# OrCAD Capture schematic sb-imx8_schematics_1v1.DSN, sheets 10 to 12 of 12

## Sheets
10 07. CSI, USB OTG, PCIe: size C; title: 07. CSI, USB OTG, PCIe
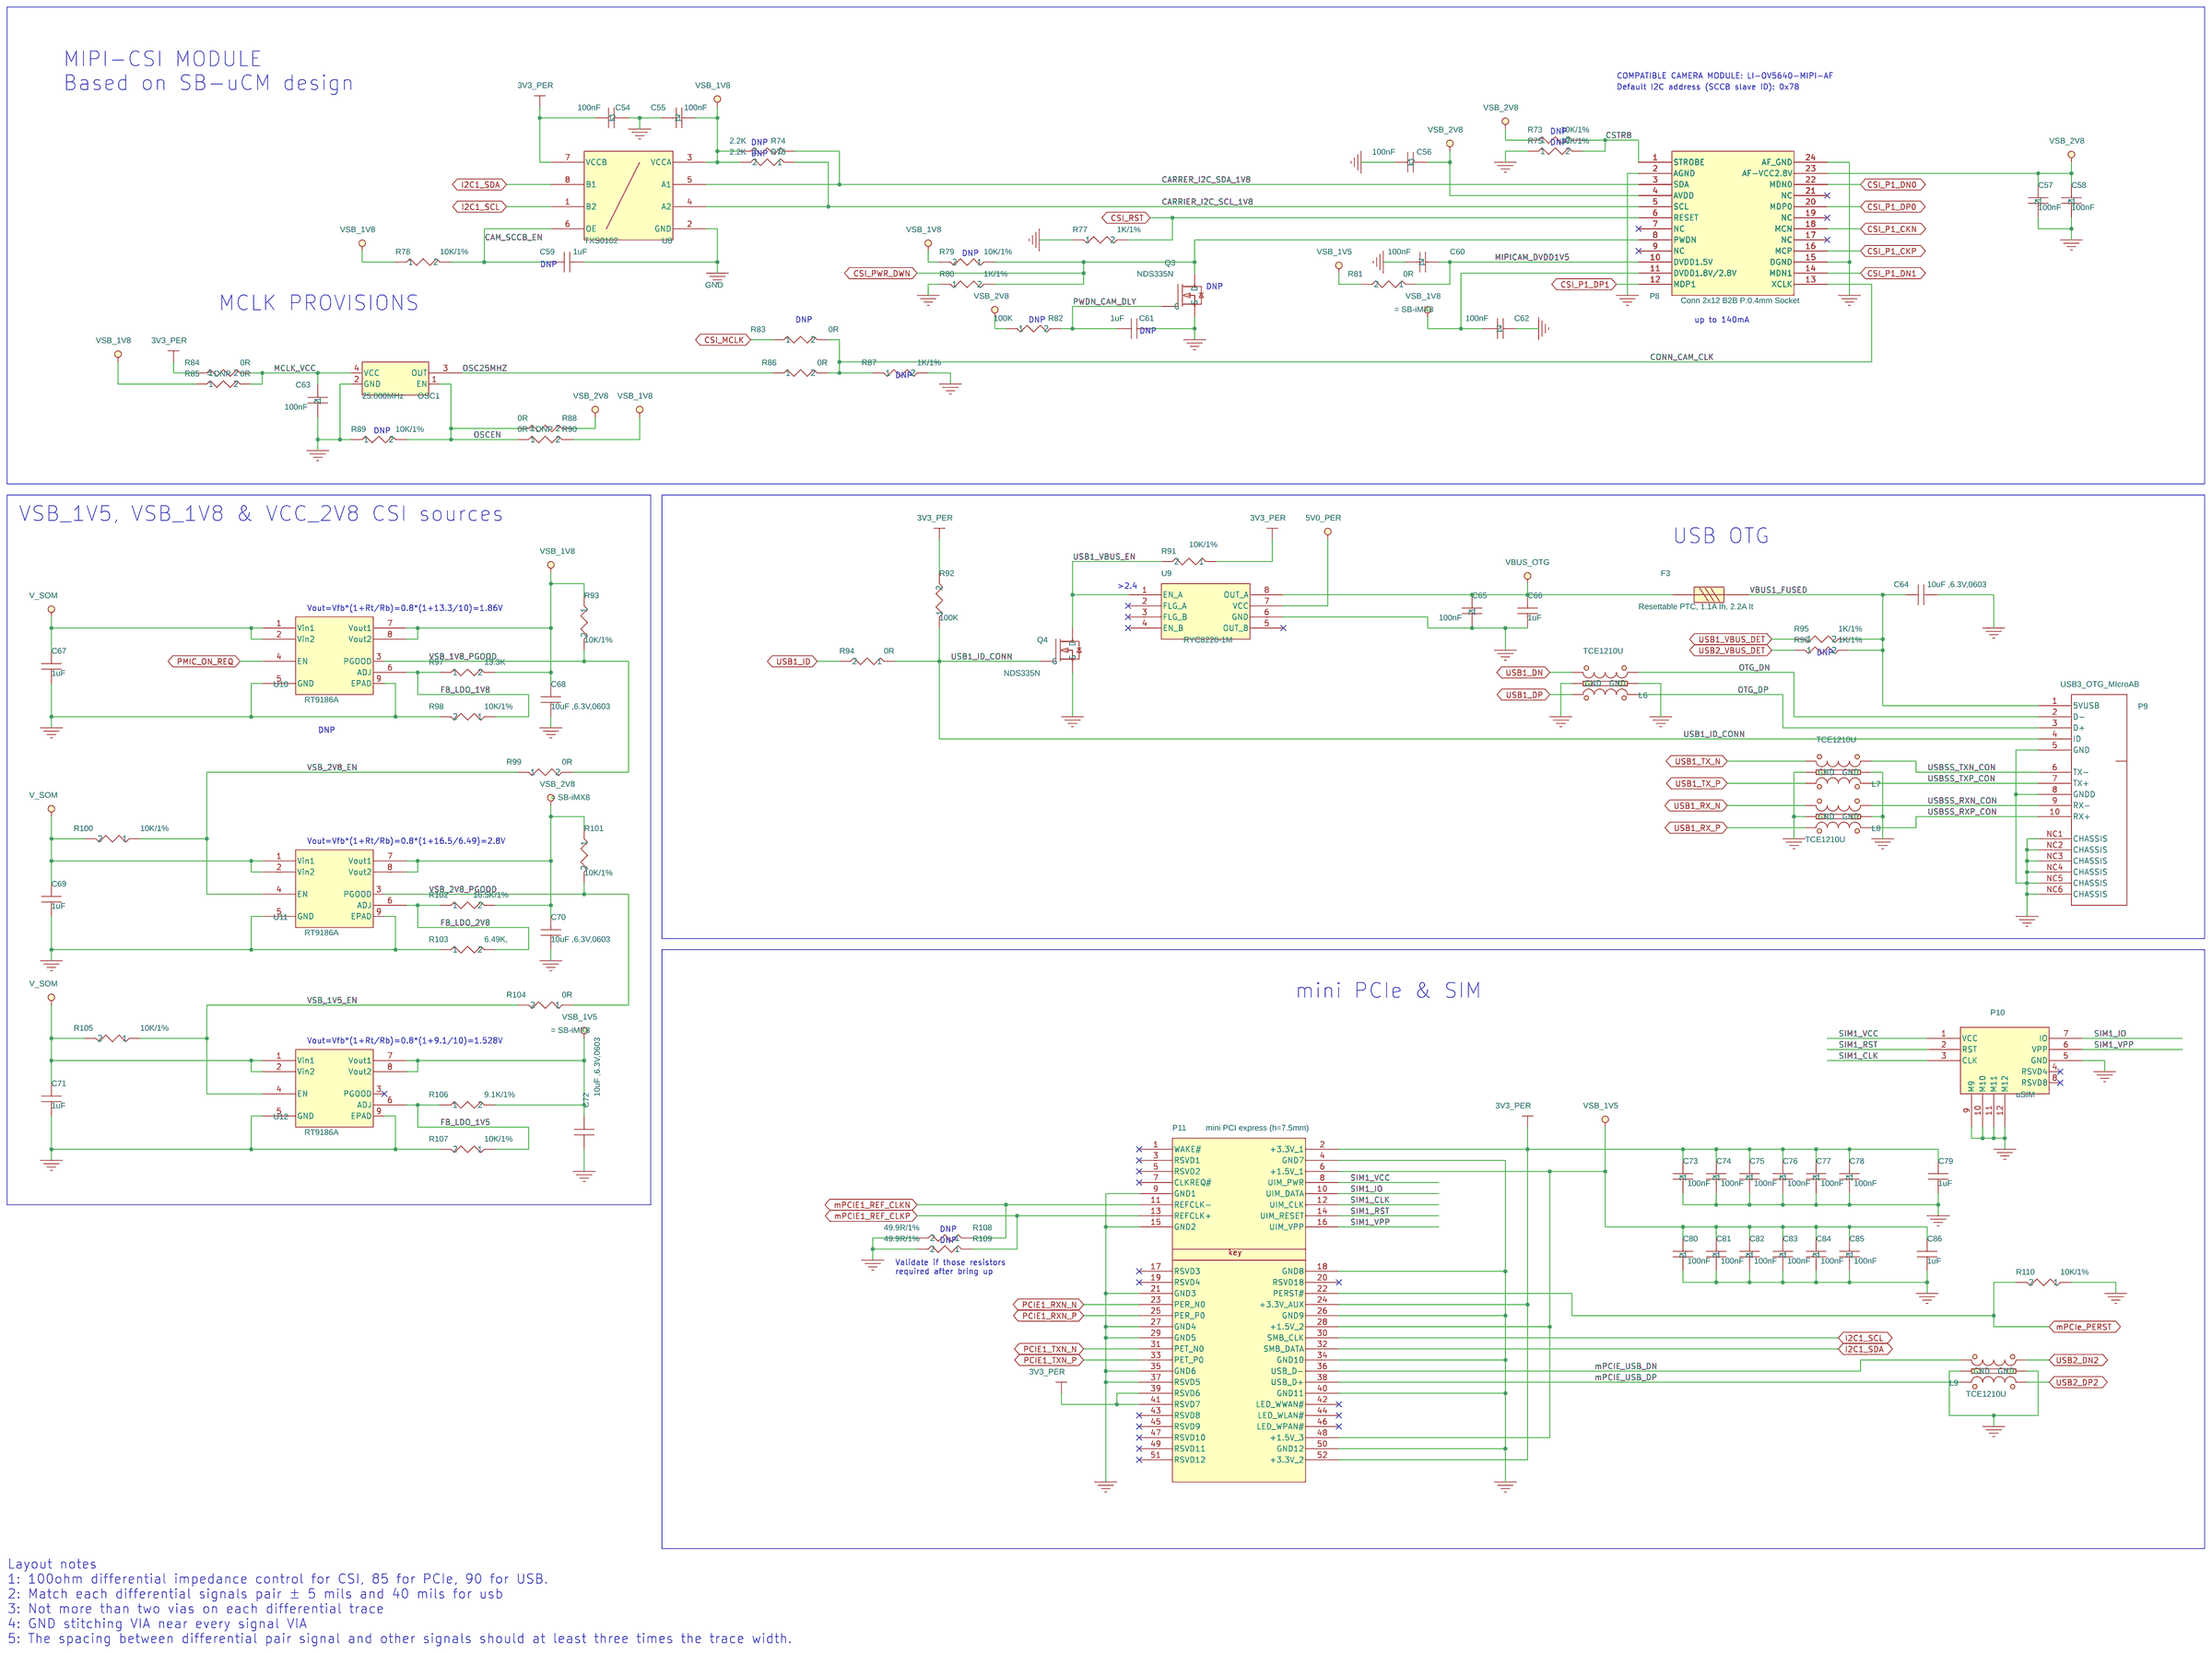
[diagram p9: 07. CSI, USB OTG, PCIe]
11 08. UART, RS232, RS485, EEPROM: size C; title: 08. UART, RS232, RS485, EEPROM
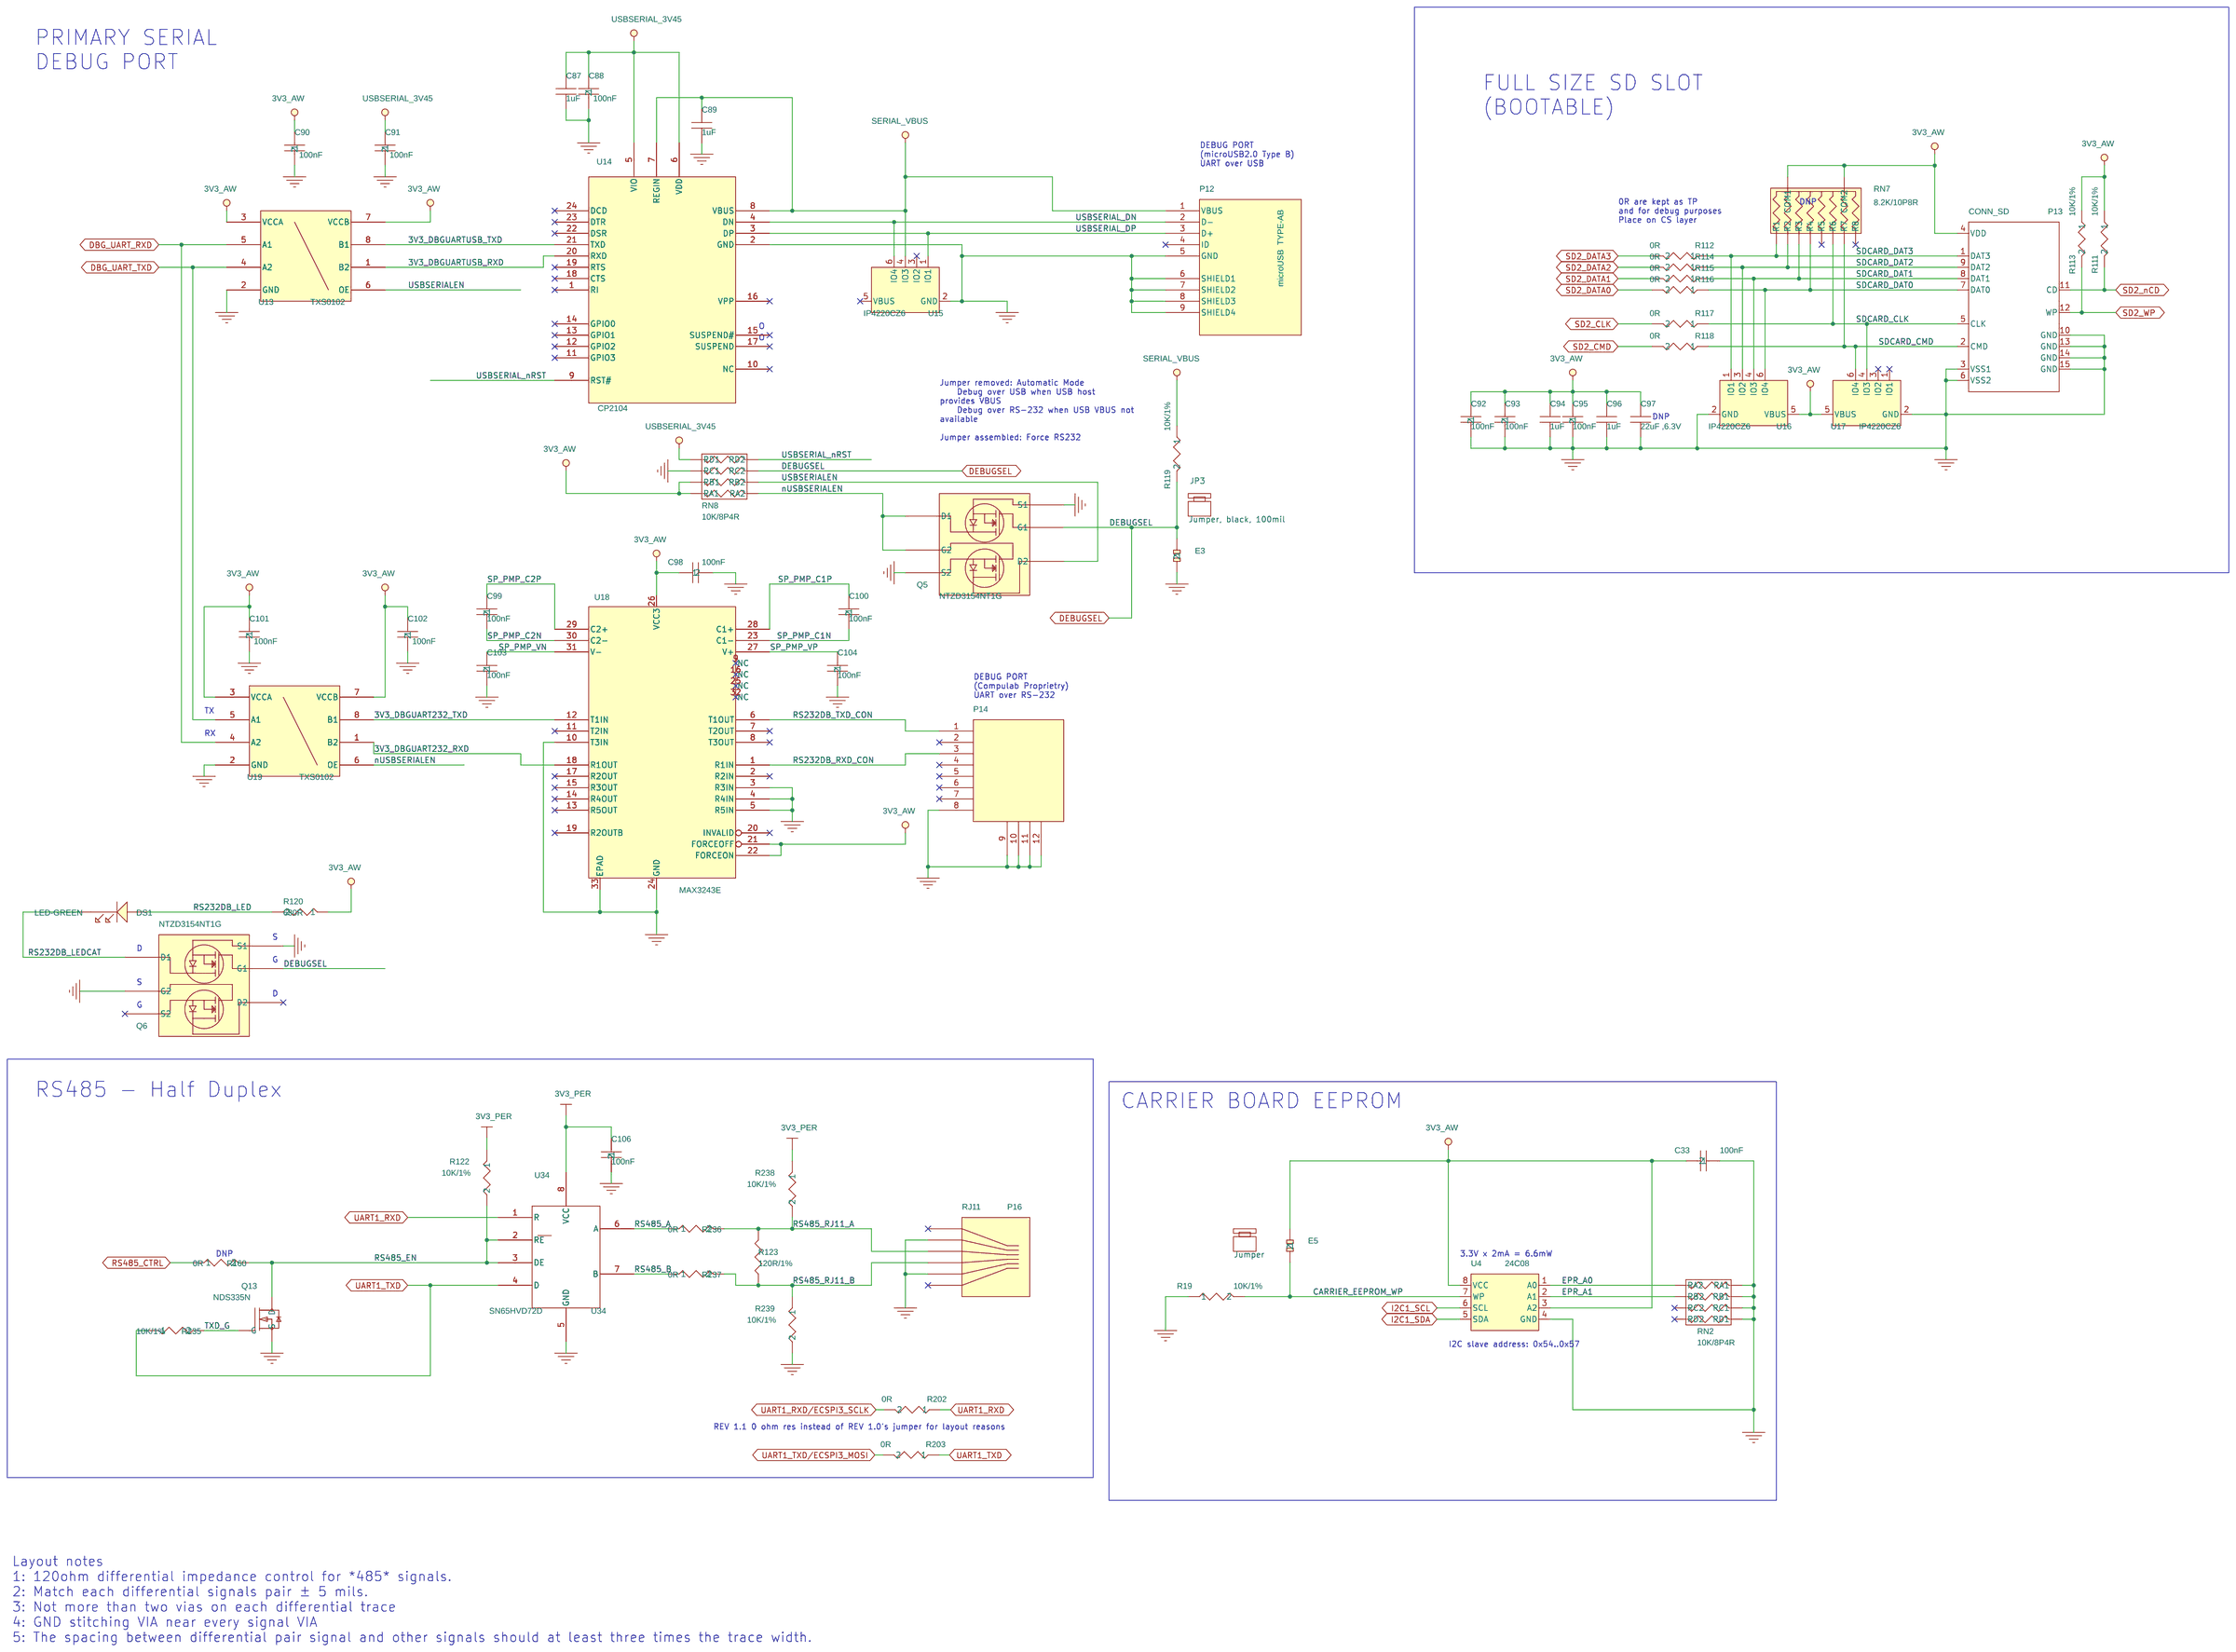
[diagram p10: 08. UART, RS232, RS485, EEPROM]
12 09. Power: size B; title: 09. Power
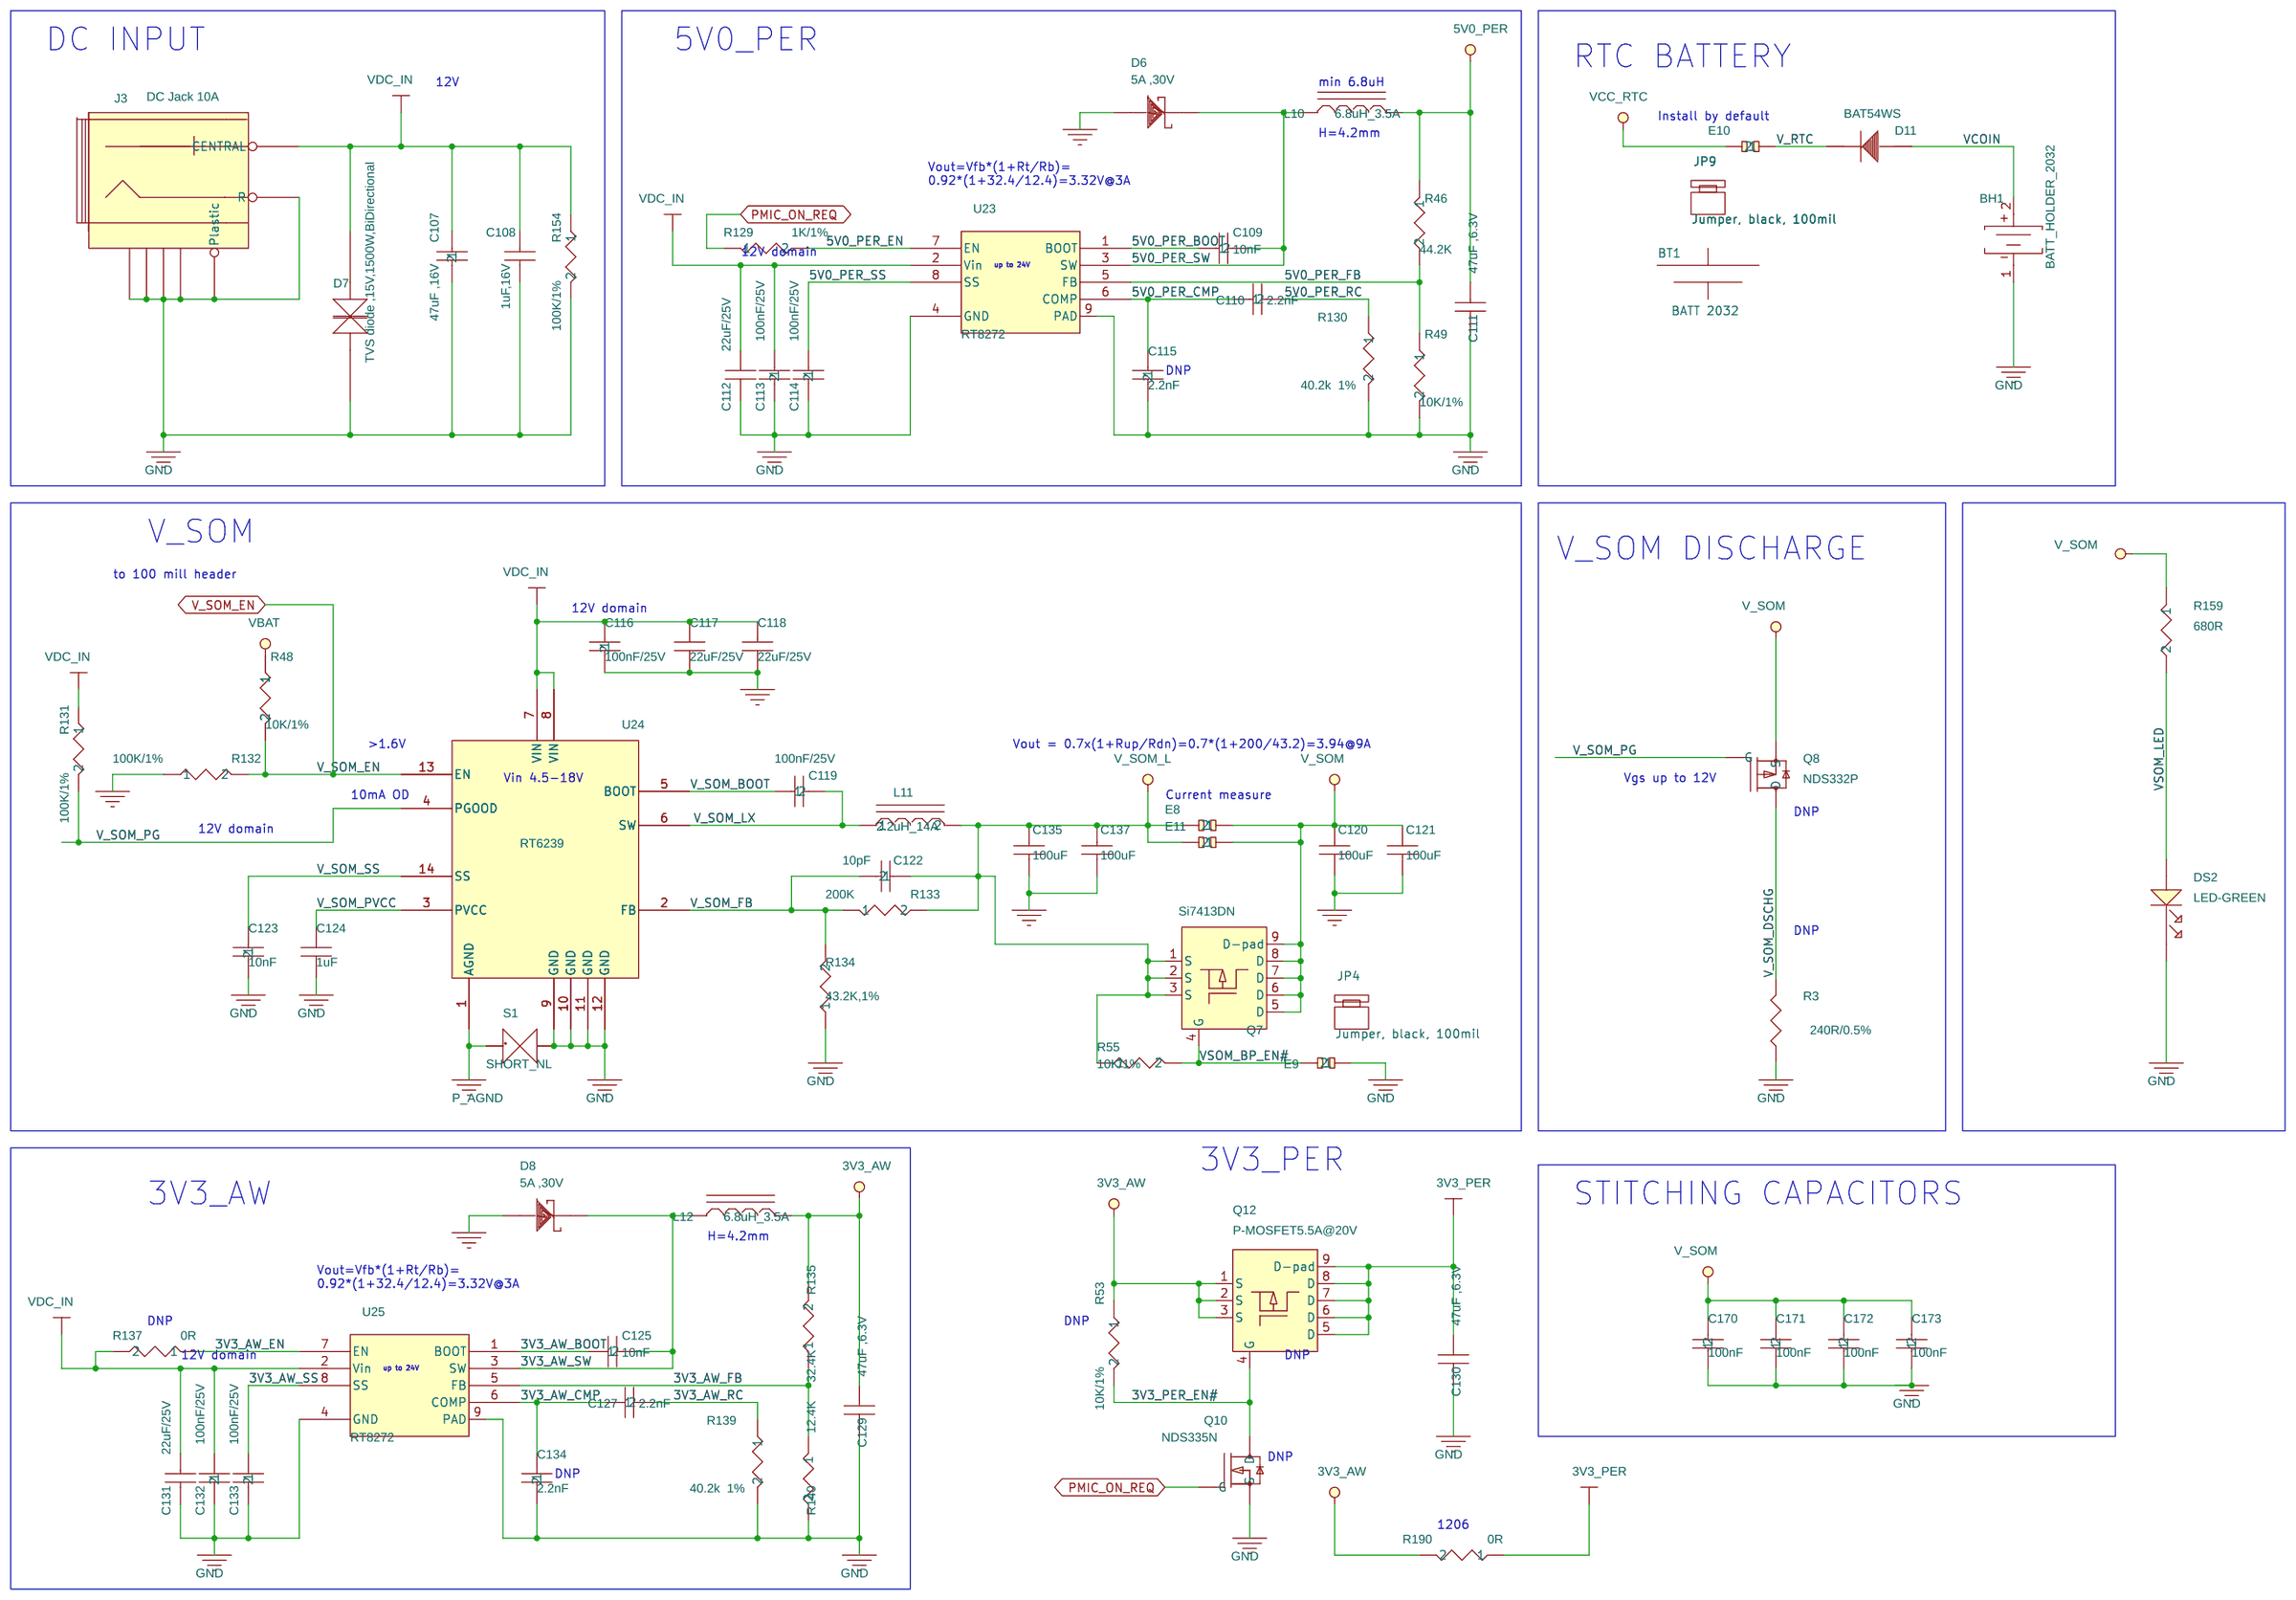
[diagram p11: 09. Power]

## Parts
sheet 07. CSI, USB OTG, PCIe
C54  100nF  [RC0402]
C55  100nF  [RC0402]
C56  100nF  [RC0402]
C57  100nF  [RC0402]
C58  100nF  [RC0402]
C59  1uF  [RC0402]
C60  100nF  [RC0402]
C61  1uF  [RC0402]
C62  100nF  [RC0402]
C63  100nF  [RC0402]
C64  10uF ,6.3V,0603  [C0603-08]
C65  100nF  [RC0402]
C66  1uF  [RC0402]
C67  1uF  [RC0402]
C68  10uF ,6.3V,0603  [C0603-08]
C69  1uF  [RC0402]
C70  10uF ,6.3V,0603  [C0603-08]
C71  1uF  [RC0402]
C72  10uF ,6.3V,0603  [C0603-08]
C73  100nF  [RC0402]
C74  100nF  [RC0402]
C75  100nF  [RC0402]
C76  100nF  [RC0402]
C77  100nF  [RC0402]
C78  100nF  [RC0402]
C79  1uF  [RC0402]
C80  100nF  [RC0402]
C81  100nF  [RC0402]
C82  100nF  [RC0402]
C83  100nF  [RC0402]
C84  100nF  [RC0402]
C85  100nF  [RC0402]
C86  1uF  [RC0402]
F3  Resettable PTC, 1.1A Ih, 2.2A It  [FUSE-1206]
L6  TCE1210U  [EMI1012-ESD]
L7  TCE1210U  [EMI1012-ESD]
L8  TCE1210U  [EMI1012-ESD]
L9  TCE1210U  [EMI1012-ESD]
OSC1  25.000MHz  [OSC3225]
P8  Conn 2x12 B2B P:0.4mm Socket  [B2B04M2X12R]
P9  USB3_OTG_MIcroAB  [MICRO-USB3-AB-RA-SM]
P10  uSIM  [SKT-MicroSIM6-SM]
P11  mini PCI express (h=7.5mm)  [MINIPCIE-4]
Q3  NDS335N  [SOT23]
Q4  NDS335N  [SOT23]
R73  10K/1%  [RC0402]
R74  2.2K  [RC0402]
R75  10K/1%  [RC0402]
R76  2.2K  [RC0402]
R77  1K/1%  [RC0402]
R78  10K/1%  [RC0402]
R79  10K/1%  [RC0402]
R80  1K/1%  [RC0402]
R81  0R  [RC0402]
R82  100K  [RC0402]
R83  0R  [RC0402]
R84  0R  [RC0402]
R85  0R  [RC0402]
R86  0R  [RC0402]
R87  1K/1%  [RC0402]
R88  0R  [RC0402]
R89  10K/1%  [RC0402]
R90  0R  [RC0402]
R91  10K/1%  [RC0402]
R92  100K  [RC0402]
R93  10K/1%  [RC0402]
R94  0R  [RC0402]
R95  1K/1%  [RC0402]
R96  1K/1%  [RC0402]
R97  13.3K  [RC0402]
R98  10K/1%  [RC0402]
R99  0R  [RC0402]
R100  10K/1%  [RC0402]
R101  10K/1%  [RC0402]
R102  16.5K/1%  [RC0402]
R103  6.49K,  [RC0402]
R104  0R  [RC0402]
R105  10K/1%  [RC0402]
R106  9.1K/1%  [RC0402]
R107  10K/1%  [RC0402]
R108  49.9R/1%  [RC0402]
R109  49.9R/1%  [RC0402]
R110  10K/1%  [RC0402]
U8  TXS0102  [MO-187DA-8]
U9  RYC8220-1M  [SO-8-150]
U10  RT9186A  [DFN3x3-8]
U11  RT9186A  [DFN3x3-8]
U12  RT9186A  [DFN3x3-8]
sheet 08. UART, RS232, RS485, EEPROM
C33  100nF  [RC0402]
C87  1uF  [RC0402]
C88  100nF  [RC0402]
C89  1uF  [RC0402]
C90  100nF  [RC0402]
C91  100nF  [RC0402]
C92  100nF  [RC0402]
C93  100nF  [RC0402]
C94  1uF  [RC0402]
C95  100nF  [RC0402]
C96  1uF  [RC0402]
C97  22uF ,6.3V  [RC0603]
C98  100nF  [RC0402]
C99  100nF  [RC0402]
C100  100nF  [RC0402]
C101  100nF  [RC0402]
C102  100nF  [RC0402]
C103  100nF  [RC0402]
C104  100nF  [RC0402]
C106  100nF  [RC0402]
DS1  LED-GREEN  [LED-1206]
E3  HDR1X2  [1X2THHDR]
E5  HDR1X2  [1X2THHDR]
JP3  Jumper, black, 100mil
JP10  Jumper
P12  microUSB  TYPE-AB  [MICRO-USB-AB-RA-SM]
P13  CONN_SD  [SD-RA-SM]
P14  Ultra Mini Serial Connector  [UMS-8]
P16  RJ11  [RJ11TH6-6]
Q5  NTZD3154NT1G  [SOT-563]
Q6  NTZD3154NT1G  [SOT-563]
Q13  NDS335N  [SOT23]
R19  10K/1%  [RC0402]
R111  10K/1%  [RC0402]
R112  0R  [RC0402]
R113  10K/1%  [RC0402]
R114  0R  [RC0402]
R115  0R  [RC0402]
R116  0R  [RC0402]
R117  0R  [RC0402]
R118  0R  [RC0402]
R119  10K/1%  [RC0402]
R120  680R  [RC0402]
R122  10K/1%  [RC0402]
R123  120R/1%  [RC0603]
R160  0R  [RC0402]
R202  0R  [RC0402]
R203  0R  [RC0402]
R235  10K/1%  [RC0402]
R236  0R  [RC0402]
R237  0R  [RC0402]
R238  10K/1%  [RC0402]
R239  10K/1%  [RC0402]
RN2  10K/8P4R  [RESNET8P0805]
RN7  8.2K/10P8R  [RESNET10P1206]
RN8  10K/8P4R  [RESNET8P0805]
U4  24C08  [MO-229VCED-2]
U13  TXS0102  [MO-187DA-8]
U14  CP2104  [MO-220VGGD-8]
U15  IP4220CZ6  [SOT23-6L]
U16  IP4220CZ6  [SOT23-6L]
U17  IP4220CZ6  [SOT23-6L]
U18  MAX3243E  [QFN5x5-32]
U19  TXS0102  [MO-187DA-8]
U34  SN65HVD72D  [MSOP-8]
sheet 09. Power
BH1  BATT_HOLDER_2032  [BATTH20MM]
BT1  BATT 2032
C107  47uF ,16V  [C1210H2_5]
C108  1uF,16V  [RC0402]
C109  10nF  [RC0402]
C110  2.2nF  [RC0402]
C111  47uF ,6.3V  [C0805]
C112  22uF/25V  [C0805]
C113  100nF/25V  [RC0402]
C114  100nF/25V  [RC0402]
C115  2.2nF  [RC0402]
C116  100nF/25V  [RC0402]
C117  22uF/25V  [C0805]
C118  22uF/25V  [C0805]
C119  100nF/25V  [RC0402]
C120  100uF  [C1210H2_5]
C121  100uF  [C1210H2_5]
C122  10pF  [RC0402]
C123  10nF  [RC0402]
C124  1uF  [RC0402]
C125  10nF  [RC0402]
C127  2.2nF  [RC0402]
C129  47uF ,6.3V  [C0805]
C130  47uF ,6.3V  [C0805]
C131  22uF/25V  [C0805]
C132  100nF/25V  [RC0402]
C133  100nF/25V  [RC0402]
C134  2.2nF  [RC0402]
C135  100uF  [C1210H2_5]
C137  100uF  [C1210H2_5]
C170  100nF  [RC0402]
C171  100nF  [RC0402]
C172  100nF  [RC0402]
C173  100nF  [RC0402]
D6  5A ,30V  [SOD-128]
D7  TVS diode ,15V,1500W,BiDirectional  [DO-214AB]
D8  5A ,30V  [SOD-128]
D11  BAT54WS  [SOD-323]
DS2  LED-GREEN  [LED-1206]
E8  HDR1X2  [1X2THHDR]
E9  HDR1X2  [1X2THHDR]
E10  HDR1X2  [1X2THHDR]
E11  HDR1X2  [1X2THHDR]
J3  DC Jack 10A  [PJ-0810-TH]
JP4  Jumper, black, 100mil
JP9  Jumper, black, 100mil
L10  6.8uH_3.5A  [IND8_2x8_2]
L11  2.2uH_14A  [IND7x7_2SM]
L12  6.8uH_3.5A  [IND8_2x8_2]
Q7  Si7413DN  [Powerpak1212-8]
Q8  NDS332P  [SOT23]
Q10  NDS335N  [SOT23]
Q12  P-MOSFET5.5A@20V  [Powerpak1212-8]
R3  240R/0.5%  [RC0402]
R46  44.2K  [RC0402]
R48  10K/1%  [RC0402]
R49  10K/1%  [RC0402]
R53  10K/1%  [RC0402]
R55  10K/1%  [RC0402]
R129  1K/1%  [RC0402]
R130  40.2k  1%  [RC0402]
R131  100K/1%  [RC0402]
R132  100K/1%  [RC0402]
R133  200K  [RC0402]
R134  43.2K,1%  [RC0402]
R135  32.4K  [RC0402]
R137  0R  [RC0402]
R139  40.2k  1%  [RC0402]
R140  12.4K  [RC0402]
R154  100K/1%  [RC0402]
R159  680R  [RC0402]
R190  0R  [RC1206]
S1  SHORT_NL  [SHORT_NL]
U23  RT8272  [PSOP-8-2X2]
U24  RT6239  [uQFN2x3-14]
U25  RT8272  [PSOP-8-2X2]

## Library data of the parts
C54 C95 C173 = 100nF,_10V,_X7R,_10%,_0402_1: CLABCONF0: = SB-iMX8
C55 = 100nF,_10V,_X7R,_10%,_0402_15: CLABCONF0: = SB-iMX8
C56 C100 = 100nF,_10V,_X7R,_10%,_0402_8: CLABCONF0: = SB-iMX8
C57 C102 = 100nF,_10V,_X7R,_10%,_0402_6: CLABCONF0: = SB-iMX8
C58 C99 = 100nF,_10V,_X7R,_10%,_0402_9: CLABCONF0: = SB-iMX8
C59 C61 = 1uF,X5R,6.3V,0402: CLABCONF0: = DNP
C60 = 100nF,_10V,_X7R,_10%,_0402_20: CLABCONF0: = SB-iMX8
C62 C88 = 100nF,_10V,_X7R,_10%,_0402_14: CLABCONF0: = SB-iMX8
C63 C92 = 100nF,_10V,_X7R,_10%,_0402_13: CLABCONF0: = SB-iMX8
C64 C68 C70 C72 = 10uF,6_0.3V,0603,20%X5R: CLABCONF0: = SB-iMX8
C65 = 100nF,_10V,_X7R,_10%,_0402_19: CLABCONF0: = SB-iMX8
C66 C67 C69 C71 C79 C86 C87 C89 C94 C96 = 1uF,X5R,6.3V,0402: CLABCONF0: = SB-iMX8
C73 C103 = 100nF,_10V,_X7R,_10%,_0402_5: CLABCONF0: = SB-iMX8
C74 = 100nF,_10V,_X7R,_10%,_0402_18: CLABCONF0: = SB-iMX8
C75 = 100nF,_10V,_X7R,_10%,_0402_17: CLABCONF0: = SB-iMX8
C33 C76 = 100nF,_10V,_X7R,_10%,_0402_4: CLABCONF0: = SB-iMX8
C77 C98 C171 = 100nF,_10V,_X7R,_10%,_0402_3: CLABCONF0: = SB-iMX8
C78 C104 = 100nF,_10V,_X7R,_10%,_0402_7: CLABCONF0: = SB-iMX8
C80 C93 = 100nF,_10V,_X7R,_10%,_0402_11: CLABCONF0: = SB-iMX8
C81 C106 = 100nF,_10V,_X7R,_10%,_0402_10: CLABCONF0: = SB-iMX8
C82 C91 = 100nF,_10V,_X7R,_10%,_0402_12: CLABCONF0: = SB-iMX8
C83 C90 C172 = 100nF,_10V,_X7R,_10%,_0402: CLABCONF0: = SB-iMX8
C84 C101 C170 = 100nF,_10V,_X7R,_10%,_0402_2: CLABCONF0: = SB-iMX8
C85 = 100nF,_10V,_X7R,_10%,_0402_16: CLABCONF0: = SB-iMX8
F3 = Fuse,_0.75A_Ih,_1.5A_It: CLABCONF0: = SB-iMX8; P/N: 175P22200S
L6-L9 = ESD_CHOKE_DIFFx2_10: CLABCONF0: = SB-iMX8; P/N: 142D11801S
OSC1 = Osc.,_50Mhz,50PPM,_3.3V: CLABCONF0: = SB-iMX8; P/N: 141C25601S
P8 = Conn_2x12_B2B_P_0.4mm_Socket: CLABCONF0: = SB-iMX8; P/N: 182K02401S
P9 = USB3_OTGMINIB_5: CLABCONF0: = SB-iMX8; P/N: 180K01000S
P10 = uSIM_SOCKET_0: CLABCONF0: = SB-iMX8
P11 = mini_PCIe_0: CLABCONF0: = SB-iMX8; P/N: 182K05201S
Q3 Q10 Q13 = N-MOSFET,NDS335N,100mOhm@2.5V: CLABCONF0: DNP
Q4 = N-MOSFET,NDS335N,100mOhm@2.5V: CLABCONF0: = SB-iMX8
R73 = 10K,1%,0402,1_16W: CLABCONF0: = DNP
R74 = 2.2K,5%,0402.1_16W: CLABCONF0: DNP
R75 = 10K,1%,0402,1_16W_11: CLABCONF0: = DNP
R76 = 2.2K,5%,0402.1_16W_1: CLABCONF0: DNP
R77 = 1K,1%,0402,1_16W_1: CLABCONF0: = SB-iMX8; Group: CAN
R78 R122 = 10K,1%,0402,1_16W_5: CLABCONF0: = SB-iMX8
R79 = 10K,1%,0402,1_16W_2: CLABCONF0: = DNP
R80 R129 = 1K,1%,0402,1_16W: CLABCONF0: = SB-iMX8; Group: CAN
R81 R203 = 0R,_0402_1_2: CLABCONF0: = SB-iMX8
R82 = 100K,_0402_1: CLABCONF0: DNP; P/N: 161C10031S
R83 R137 = 0R,_0402_1: CLABCONF0: DNP
R84 R112 = 0R,_0402_1_1: CLABCONF0: = SB-iMX8
R85 = 0R,_0402_1_7: CLABCONF0: = DNP
R86 R236 = 0R,_0402_1_3: CLABCONF0: = SB-iMX8
R87 = 1K,1%,0402,1_16W_4: CLABCONF0: DNP; Group: CAN
R88 R237 = 0R,_0402_1_6: CLABCONF0: = SB-iMX8
R89 = 10K,1%,0402,1_16W_6: CLABCONF0: = DNP
R90 = 0R,_0402_1_9: CLABCONF0: = DNP
R91 = 10K,1%,0402,1_16W_8: CLABCONF0: = SB-iMX8
R92 = 100K,_0402: CLABCONF0: = SB-iMX8; P/N: 161C10031S
R93 R235 = 10K,1%,0402,1_16W_3: CLABCONF0: = SB-iMX8
R94 R116 = 0R,_0402_1_8: CLABCONF0: = SB-iMX8
R95 = 1K,1%,0402,1_16W_2: CLABCONF0: = SB-iMX8; Group: CAN
R96 = 1K,1%,0402,1_16W_3: CLABCONF0: DNP; Group: CAN
R97 = 13.3K,_0402_tmp: CLABCONF0: = SB-iMX8; P/N: 161C13321S
R98 = 10K,1%,0402,1_16W_13: CLABCONF0: = SB-iMX8
R99 R114 = 0R,_0402_1_4: CLABCONF0: = SB-iMX8
R100 = 10K,1%,0402,1_16W_12: CLABCONF0: = SB-iMX8
R101 = 10K,1%,0402,1_16W_9: CLABCONF0: = SB-iMX8
R102 = 10K,1%,0402,1_16W_4: CLABCONF0: = SB-iMX8; P/N: 161C16521S
R103 = 33R,5%,0402,1_16W: CLABCONF0: = SB-iMX8; P/N: 161C64911S
R104 R115 = 0R,_0402_1_5: CLABCONF0: = SB-iMX8
R48 R105 R239 = 10K,1%,0402,1_16W_1: CLABCONF0: = SB-iMX8
R106 = 953R,1%,0402,1_16W_0: CLABCONF0: = SB-iMX8; P/N: 161C91011S
R107 = 10K,1%,0402,1_16W_10: CLABCONF0: = SB-iMX8
R108 = 49.9R_1%,_0402: CLABCONF0: = DNP
R109 = 49.9R_1%,_0402_1: CLABCONF0: = DNP
R110 R111 = 10K,1%,0402,1_16W_7: CLABCONF0: = SB-iMX8
U8 U13 U19 = TXS0102_0: CLABCONF0: = SB-iMX8; P/N: 116A01020S
U9 = RYC8220-1M_DUAL_USB_PWR_SWITCH: CLABCONF0: = SB-iMX8
U10-U12 = RT9186A,LDO_,2.5-5_0.5V,500mA: CLABCONF0: = SB-iMX8
C97 = 22uF,6.3V,X5R: CLABCONF0: = SB-iMX8; P/N: 151B22610S
DS1 DS2 = LED-GREEN_1206_3: CLABCONF0: = SB-iMX8
E3 E8 = HDR_1x2_100MIL_TH_JUMPER_1: CLABCONF0: = SB-iMX8
E5 E9 = HDR_1x2_100MIL_TH_JUMPER: CLABCONF0: = SB-iMX8
JP3 JP10 = Jumper,_black,_100mil_0: CLABCONF0: = SB-iMX8
P12 = Conn.,_Micro-USB,_B-Type: CLABCONF0: = SB-iMX8; P/N: 180K00501S
P13 = SDIO_SLOT: CLABCONF0: = SB-iMX8
P14 = Ultra_Mini_Serial_Connector: CLABCONF0: = SB-iMX8
P16 = RJ11: CLABCONF0: = SB-iMX8
Q5 Q6 = MOSFET_N_DUAL_0_0.4A_20V: CLABCONF0: = SB-iMX8
R19 = 10K,1%,0402,1_16W_4: CLABCONF0: = SB-iMX8
R113 = 10K,1%,0402,1_16W_6: CLABCONF0: = SB-iMX8
R117 = 0R,_0402_1_9: CLABCONF0: = SB-iMX8
R118 = 0R,_0402_1_10: CLABCONF0: = SB-iMX8
R49 R119 = 10K,1%,0402,1_16W_2: CLABCONF0: = SB-iMX8
R120 R159 = 47K,_0402: CLABCONF0: = SB-iMX8; P/N: 161C68001S
R123 = 120R_1%,_0603: CLABCONF0: = SB-iMX8
R160 = 0R,_0402_1_7: CLABCONF0: DNP
R202 = 0R,_0402_1: CLABCONF0: = SB-iMX8
R55 R238 = 10K,1%,0402,1_16W: CLABCONF0: = SB-iMX8
RN2 RN8 = RN,10K,8P4R@0805: CLABCONF0: = SB-iMX8
RN7 = RN,8.2K,10P8R@1206: CLABCONF0: = DNP
U4 = 24C02,_serial_EE,_2KB,_I2C: CLABCONF0: = SB-iMX8; P/N: 111S31000S
U14 = CP2104_0: CLABCONF0: = SB-iMX8; P/N: 116A00140S
U15-U17 = IP4220CZ6_0: CLABCONF0: = SB-iMX8
U18 = MAX3243E_RS-232_3T5R_BGA: CLABCONF0: = SB-iMX8
U34 = SN65HVD72D_1: PN: 116A00310S
BH1 = BATT_HOLDER_0: CLABCONF0: = SB-iMX8
BT1 = BATT_2032: CLABCONF0: = SB-iMX8
C107 = Cap.,_47uF,_16V,_X5R: CLABCONF0: = SB-iMX8
C108 C124 = 1uF,16V,0402: CLABCONF0: = SB-iMX8
C109 = 10nF,_25V,_X7R,_10%,_0402_2: CLABCONF0: = SB-iMX8
C110 = 2.2nF,_50V,_X7R,_10%,_0402_3: CLABCONF0: = SB-iMX8
C111 = 47uF,6.3V,X5R: CLABCONF0: = SB-iMX8
C112 = Cap.,22uF,25V,_0805_1: CLABCONF0: = SB-iMX8
C113 = 100nF_0402_25V_2: CLABCONF0: = SB-iMX8
C114 = 100nF_0402_25V: CLABCONF0: = SB-iMX8
C115 = 2.2nF,_50V,_X7R,_10%,_0402: CLABCONF0: = DNP
C116 = 100nF_0402_25V_5: CLABCONF0: = SB-iMX8
C117 = 22uF,25V,_0805_1: CLABCONF0: = SB-iMX8
C118 = 22uF,25V,_0805: CLABCONF0: = SB-iMX8
C119 = 100nF_0402_25V_4: CLABCONF0: = SB-iMX8
C120 C121 C135 C137 = 100uF,_6.3V,_X5R,_20%,_1206: CLABCONF0: = SB-iMX8
C122 = 10pF,50V,NPO,_5%,_0402: CLABCONF0: = SB-iMX8
C123 = 10nF,_25V,_X7R,_10%,_0402: CLABCONF0: = SB-iMX8
C125 = 10nF,_25V,_X7R,_10%,_0402_1: CLABCONF0: = SB-iMX8
C127 = 2.2nF,_50V,_X7R,_10%,_0402_1: CLABCONF0: = SB-iMX8
C129 = 47uF,6.3V,X5R_1: CLABCONF0: = SB-iMX8
C130 = 47uF,6.3V,X5R_2: CLABCONF0: = SB-iMX8
C131 = Cap.,22uF,25V,_0805: CLABCONF0: = SB-iMX8
C132 = 100nF_0402_25V_1: CLABCONF0: = SB-iMX8
C133 = 100nF_0402_25V_3: CLABCONF0: = SB-iMX8
C134 = 2.2nF,_50V,_X7R,_10%,_0402_2: CLABCONF0: DNP
D6 D8 = Diode_Shotky,5A,30V: CLABCONF0: = SB-iMX8
D7 = Diode_,TVS_,15V,1500W_0: CLABCONF0: = SB-iMX8; P/N: 132D00150S
D11 = BAT54WS_0: CLABCONF0: = SB-iMX8
E10 = HDR_1x2_100MIL_TH_JUMPER_2: CLABCONF0: = SB-iMX8
E11 = HDR_1x2_100MIL_TH_JUMPER_3: CLABCONF0: = SB-iMX8
J3 = DC_Jack_,5.5_2_0.5,10A,20V: CLABCONF0: = SB-iMX8
JP4 JP9 = Jumper,_black,_100mil: CLABCONF0: = SB-iMX8
L10 L12 = IND_6.8uH_3.5A: CLABCONF0: = SB-iMX8; P/N: 147A6R801S
L11 = IND_DELTA_MPL73-2R2_2.2uH_14A: CLABCONF0: = SB-iMX8
Q7 = Si7413DN: CLABCONF0: = SB-iMX8
Q8 = P-MOSFET,3A,20V,110mOhm@-1.8V: CLABCONF0: = DNP
Q12 = MOSFET_P,_5.5A_20V: CLABCONF0: DNP
R3 = 240R_resistor,_%0.5: CLABCONF0: = DNP; P/N: 161C24003S
R46 = 100K,_0402_1: CLABCONF0: = SB-iMX8; P/N: 161C44221S
R53 = 10K,1%,0402,1_16W_3: CLABCONF0: DNP
R130 = 40.2k_,1%: CLABCONF0: = SB-iMX8
R131 = 100K,_1%,_0402,_1_16W: CLABCONF0: = SB-iMX8
R132 = 100K,_1%,_0402,_1_16W_2: CLABCONF0: = SB-iMX8
R133 = 100K,_0402: CLABCONF0: = SB-iMX8; P/N: 161C20031S
R134 = 43.2K,1%,0402: CLABCONF0: = SB-iMX8
R135 = 32.4K,_0402: CLABCONF0: = SB-iMX8; P/N: 161C32421S
R139 = 40.2k_,1%_1: CLABCONF0: = SB-iMX8
R140 = 4.99K,1%,0402,1_16W: CLABCONF0: = SB-iMX8; P/N: 161C12421S
R154 = 100K,_1%,_0402,_1_16W_1: CLABCONF0: = SB-iMX8
R190 = 0R,_1206: CLABCONF0: = SB-iMX8
S1 = MISC_SHORT_NL: CLABCONF0: = SB-iMX8
U23 U25 = RT8272,Converter,3A,24V: CLABCONF0: = SB-iMX8
U24 = RT6239A_B: CLABCONF0: = SB-iMX8; P/N: 123V08000S

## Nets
3V3_AW: C33.2 C90.1 C92.1 C93.1 C94.1 C95.1 C96.1 C97.1 C98.1 C101.1 C102.1 C129.1 E5.1 L12.2 P13.4(VDD) Q12.1(S) Q12.2(S) Q12.3(S) R48.1 R53.1 R111.1 R113.1 R120.1 R135.2 R190.2 RN7.5(COM1) RN7.10(COM2) RN8.1(RA1) RN8.2(RB1) U4.3(A2) U4.8(VCC) U13.3(VCCA) U13.7(VCCB) U16.5(VBUS) U17.5(VBUS) U18.21(FORCEOFF) U18.22(FORCEON) U18.26(VCC3) U19.3(VCCA) U19.7(VCCB) ; also on sheet 7 9
3V3_AW_BOOT: C125.1 U25.1(BOOT)
3V3_AW_CMP: C127.1 C134.1 U25.6(COMP)
3V3_AW_EN: R137.1 U25.7(EN)
3V3_AW_FB: R135.1 R140.1 U25.5(FB)
3V3_AW_RC: C127.2 R139.1
3V3_AW_SS: C133.1 U25.8(SS)
3V3_AW_SW: C125.2 D8.CATHODE L12.1 U25.3(SW)
3V3_DBGUART232_RXD: U18.18(R1OUT) U19.1(B2)
3V3_DBGUART232_TXD: U18.12(T1IN) U19.8(B1)
3V3_DBGUARTUSB_RXD: U13.1(B2) U14.20(RXD)
3V3_DBGUARTUSB_TXD: U13.8(B1) U14.21(TXD)
3V3_PER: C54.1 C73.1 C74.1 C75.1 C76.1 C77.1 C78.1 C79.1 C106.1 C130.1 P11.2(+3.3V_1) P11.24(+3.3V_AUX) P11.39(RSVD6) P11.41(RSVD7) P11.52(+3.3V_2) Q12.5(D) Q12.6(D) Q12.7(D) Q12.8(D) Q12.9(D-pad) R84.1 R91.1 R92.2 R122.1 R190.1 R238.1 U8.7(VCCB) U34.8(VCC) ; also on sheet 1 2 7 8 9
3V3_PER_EN#: Q10.3(D) Q12.4(G) R53.2
5V0_PER: C111.1 L10.2 R46.1 U9.7(VCC) ; also on sheet 2 7 8 9
5V0_PER_BOOT: C109.1 U23.1(BOOT)
5V0_PER_CMP: C110.1 C115.1 U23.6(COMP)
5V0_PER_EN: R129.2 U23.7(EN)
5V0_PER_FB: R46.2 R49.1 U23.5(FB)
5V0_PER_RC: C110.2 R130.1
5V0_PER_SS: C114.1 U23.8(SS)
5V0_PER_SW: C109.2 D6.CATHODE L10.1 U23.3(SW)
GND: BH1.1(MINUS) C33.1 C54.2 C55.2 C56.1 C57.2 C58.2 C59.2 C60.2 C61.1 C62.1 C63.2 C64.2 C65.2 C66.2 C67.2 C68.2 C69.2 C70.2 C71.2 C72.2 C73.2 C74.2 C75.2 C76.2 C77.2 C78.2 C79.2 C80.2 C81.2 C82.2 C83.2 C84.2 C85.2 C86.2 C87.2 C88.2 C89.2 C90.2 C91.2 C92.2 C93.2 C94.2 C95.2 C96.2 C97.2 C98.2 C101.2 C102.2 C103.2 C104.2 C106.2 C107.2 C108.2 C111.2 C112.2 C113.2 C114.2 C115.2 C116.2 C117.2 C118.2 C120.1 C121.1 C123.2 C124.2 C129.2 C130.2 C131.2 C132.2 C133.2 C134.2 C135.1 C137.1 C170.1 C171.1 C172.1 C173.1 D6.ANODE D7.ANODE D8.ANODE DS2.CATHODE E3.2 E9.1 J3.2(R) J3.3(Plastic) J3.SH1 J3.SH2 J3.SH3 J3.SH4 L6.5(GND) L6.6(GND) L7.5(GND) L7.6(GND) L8.5(GND) L8.6(GND) L9.5(GND) L9.6(GND) OSC1.2(GND) P8.2(AGND) P8.15(DGND) P8.24(AF_GND) P9.5(GND) P9.8(GNDD) P9.NC1(CHASSIS) P9.NC2(CHASSIS) P9.NC3(CHASSIS) P9.NC4(CHASSIS) P9.NC5(CHASSIS) P9.NC6(CHASSIS) P10.5(GND) P10.9(M9) P10.10(M10) P10.11(M11) P10.12(M12) P11.4(GND7) P11.9(GND1) P11.15(GND2) P11.18(GND8) P11.21(GND3) P11.26(GND9) P11.27(GND4) P11.29(GND5) P11.34(GND10) P11.35(GND6) P11.37(RSVD5) P11.40(GND11) P11.50(GND12) P12.5(GND) P12.6(SHIELD1) P12.7(SHIELD2) P12.8(SHIELD3) P12.9(SHIELD4) P13.3(VSS1) P13.6(VSS2) P13.10(GND) P13.13(GND) P13.14(GND) P13.15(GND) P14.8 P14.9(CHASSIS) P14.10(CHASSIS) P14.11(CHASSIS) P14.12(CHASSIS) P16.2 P16.5 Q3.2(S) Q4.2(S) Q5.1(S1) Q5.4(S2) Q6.1(S1) Q6.5(G2) Q10.2(S) Q13.2(S) R3.2 R19.1 R49.2 R75.1 R77.1 R80.1 R87.2 R89.1 R98.2 R103.1 R107.2 R108.2 R109.2 R110.1 R130.2 R132.1 R134.1 R139.2 R140.2 R154.2 R239.2 RN2.1(RA1) RN2.2(RB1) RN2.3(RC1) RN2.4(RD1) RN8.3(RC1) S1.2 U4.4(GND) U8.2(GND) U9.6(GND) U10.5(GND) U10.9(EPAD) U11.5(GND) U11.9(EPAD) U12.5(GND) U12.9(EPAD) U13.2(GND) U14.2(GND) U15.2(GND) U16.2(GND) U17.2(GND) U18.3(R3IN) U18.4(R4IN) U18.5(R5IN) U18.10(T3IN) U18.24(GND) U18.33(EPAD) U19.2(GND) U23.4(GND) U23.9(PAD) U24.9(GND) U24.10(GND) U24.11(GND) U24.12(GND) U25.4(GND) U25.9(PAD) U34.5(GND) ; also on sheet 1 2 3 5 6 7 8 9
VBUS1_FUSED: C64.1 F3.1 P9.1(5VUSB) R95.2 R96.2
VBUS_OTG: C65.1 C66.1 F3.2 U9.8(OUT_A)
VCC_RTC: E10.2 ; also on sheet 5
CAM_SCCB_EN: C59.1 R78.2 U8.6(OE)
CARRER_I2C_SDA_1V8: P8.3(SDA) R74.1 U8.5(A1)
CARRIER_EEPROM_WP: E5.2 R19.2 U4.7(WP)
CARRIER_I2C_SCL_1V8: P8.5(SCL) R76.1 U8.4(A2)
CONN_CAM_CLK: P8.13(XCLK) R83.2 R86.2 R87.1
CSI_MCLK: R83.1 ; also on sheet 7
CSI_P1_CKN: P8.18(MCN) ; also on sheet 5
CSI_P1_CKP: P8.16(MCP) ; also on sheet 5
CSI_P1_DN0: P8.22(MDN0) ; also on sheet 5
CSI_P1_DN1: P8.14(MDN1) ; also on sheet 5
CSI_P1_DP0: P8.20(MDP0) ; also on sheet 5
CSI_P1_DP1: P8.12(MDP1) ; also on sheet 5
CSI_PWR_DWN: P8.8(PWDN) Q3.3(D) R79.1 R80.2 ; also on sheet 7
CSI_RST: P8.6(RESET) R77.2 ; also on sheet 7
CSTRB: P8.1(STROBE) R73.2 R75.2
DBG_UART_RXD: U13.5(A1) U19.4(A2) ; also on sheet 5
DBG_UART_TXD: U13.4(A2) U19.5(A1) ; also on sheet 5
DEBUGSEL: E3.1 Q5.2(G1) Q6.2(G1) R119.2 RN8.6(RC2) ; also on sheet 7
EPR_A0: RN2.8(RA2) U4.1(A0)
EPR_A1: RN2.7(RB2) U4.2(A1)
FB_LDO_1V5: R106.1 R107.1 U12.6(ADJ)
FB_LDO_1V8: R97.1 R98.1 U10.6(ADJ)
FB_LDO_2V8: R102.1 R103.2 U11.6(ADJ)
I2C1_SCL: P11.30(SMB_CLK) U4.6(SCL) U8.1(B2) ; also on sheet 1 5 7
I2C1_SDA: P11.32(SMB_DATA) U4.5(SDA) U8.8(B1) ; also on sheet 1 5 7
MCLK_VCC: C63.1 OSC1.4(VCC) R84.2 R85.2
MIPICAM_DVDD1V5: C60.1 P8.10(DVDD1.5V) R81.1
mPCIE1_REF_CLKN: P11.11(REFCLK-) R108.1 ; also on sheet 7
mPCIE1_REF_CLKP: P11.13(REFCLK+) R109.1 ; also on sheet 7
mPCIe_PERST: P11.22(PERST#) R110.2 ; also on sheet 7
mPCIE_USB_DN: L9.4 P11.36(USB_D-)
mPCIE_USB_DP: L9.3 P11.38(USB_D+)
nUSBSERIALEN: Q5.5(G2) Q5.6(D1) RN8.8(RA2) U19.6(OE)
OSC25MHZ: OSC1.3(OUT) R86.1
OSCEN: OSC1.1(EN) R88.1 R89.2 R90.1
OTG_DN: L6.2 P9.2(D-)
OTG_DP: L6.1 P9.3(D+)
P_AGND: S1.1 U24.1(AGND)
PCIE1_RXN_N: P11.23(PER_N0) ; also on sheet 5
PCIE1_RXN_P: P11.25(PER_P0) ; also on sheet 5
PCIE1_TXN_N: P11.31(PET_N0) ; also on sheet 5
PCIE1_TXN_P: P11.33(PET_P0) ; also on sheet 5
PMIC_ON_REQ: Q10.1(G) R129.1 U10.4(EN) ; also on sheet 5 8 9
PWDN_CAM_DLY: C61.2 Q3.1(G) R82.2
RS232DB_LED: DS1.ANODE R120.2
RS232DB_LEDCAT: DS1.CATHODE Q6.6(D1)
RS232DB_RXD_CON: P14.3 U18.1(R1IN)
RS232DB_TXD_CON: P14.1 U18.6(T1OUT)
RS485_A: R236.1 U34.6(A)
RS485_B: R237.1 U34.7(B)
RS485_CTRL: R160.1 ; also on sheet 7
RS485_EN: Q13.3(D) R122.2 R160.2 U34.2(RE) U34.3(DE)
RS485_RJ11_A: P16.3 R123.2 R236.2 R238.2
RS485_RJ11_B: P16.4 R123.1 R237.2 R239.1
SD2_CLK: R117.2 ; also on sheet 5
SD2_CMD: R118.2 ; also on sheet 5
SD2_DATA0: R116.2 ; also on sheet 5
SD2_DATA1: R115.2 ; also on sheet 5
SD2_DATA2: R114.2 ; also on sheet 5
SD2_DATA3: R112.2 ; also on sheet 5
SD2_nCD: P13.11(CD) R111.2 ; also on sheet 5
SD2_WP: P13.12(WP) R113.2 ; also on sheet 5
SDCARD_CLK: P13.5(CLK) R117.1 RN7.7(R6) U17.4(IO3)
SDCARD_CMD: P13.2(CMD) R118.1 RN7.8(R7) U17.6(IO4)
SDCARD_DAT0: P13.7(DAT0) R116.1 RN7.4(R4) U16.6(IO4)
SDCARD_DAT1: P13.8(DAT1) R115.1 RN7.3(R3) U16.4(IO3)
SDCARD_DAT2: P13.9(DAT2) R114.1 RN7.2(R2) U16.3(IO2)
SDCARD_DAT3: P13.1(DAT3) R112.1 RN7.1(R1) U16.1(IO1)
SERIAL_VBUS: C89.1 P12.1(VBUS) R119.1 U14.7(REGIN) U14.8(VBUS) U15.4(IO3)
SIM1_CLK: P10.3(CLK) P11.12(UIM_CLK)
SIM1_IO: P10.7(IO) P11.10(UIM_DATA)
SIM1_RST: P10.2(RST) P11.14(UIM_RESET)
SIM1_VCC: P10.1(VCC) P11.8(UIM_PWR)
SIM1_VPP: P10.6(VPP) P11.16(UIM_VPP)
SP_PMP_C1N: C100.2 U18.23(C1-)
SP_PMP_C1P: C100.1 U18.28(C1+)
SP_PMP_C2N: C99.2 U18.30(C2-)
SP_PMP_C2P: C99.1 U18.29(C2+)
SP_PMP_VN: C103.1 U18.31(V-)
SP_PMP_VP: C104.1 U18.27(V+)
TXD_G: Q13.1(G) R235.2
UART1_RXD: R202.1 U34.1(R) ; also on sheet 9
UART1_RXD/ECSPI3_SCLK: R202.2 ; also on sheet 5
UART1_TXD: R203.1 R235.1 U34.4(D) ; also on sheet 9
UART1_TXD/ECSPI3_MOSI: R203.2 ; also on sheet 5
USB1_DN: L6.3 ; also on sheet 5
USB1_DP: L6.4 ; also on sheet 5
USB1_ID: R94.2 ; also on sheet 5
USB1_ID_CONN: P9.4(ID) Q4.1(G) R92.1 R94.1
USB1_RX_N: L8.3 ; also on sheet 5
USB1_RX_P: L8.4 ; also on sheet 5
USB1_TX_N: L7.3 ; also on sheet 5
USB1_TX_P: L7.4 ; also on sheet 5
USB1_VBUS_DET: R95.1 ; also on sheet 5 8
USB1_VBUS_EN: Q4.3(D) R91.2 U9.1(EN_A)
USB2_DN2: L9.1 ; also on sheet 8
USB2_DP2: L9.2 ; also on sheet 8
USB2_VBUS_DET: R96.1 ; also on sheet 5 8
USBSERIAL_3V45: C87.1 C88.1 C91.1 RN8.4(RD1) U14.5(VIO) U14.6(VDD)
USBSERIAL_DN: P12.2(D-) U14.4(DN) U15.6(IO4)
USBSERIAL_DP: P12.3(D+) U14.3(DP) U15.1(IO1)
USBSERIAL_nRST: RN8.5(RD2) U14.9(RST#)
USBSERIALEN: Q5.3(D2) RN8.7(RB2) U13.6(OE)
USBSS_RXN_CON: L8.2 P9.9(RX-)
USBSS_RXP_CON: L8.1 P9.10(RX+)
USBSS_TXN_CON: L7.2 P9.6(TX-)
USBSS_TXP_CON: L7.1 P9.7(TX+)
V_RTC: D11.CATHODE E10.1
V_SOM: C67.1 C69.1 C71.1 C120.2 C121.2 C170.2 C171.2 C172.2 C173.2 E8.1 E11.1 Q7.5(D) Q7.6(D) Q7.7(D) Q7.8(D) Q7.9(D-pad) Q8.2(S) R100.2 R105.2 R159.1 U10.1(Vin1) U10.2(Vin2) U11.1(Vin1) U11.2(Vin2) U12.1(Vin1) U12.2(Vin2) ; also on sheet 5 8
V_SOM_BOOT: C119.1 U24.5(BOOT)
V_SOM_DSCHG: Q8.3(D) R3.1
V_SOM_EN: R48.2 R132.2 U24.13(EN) ; also on sheet 9
V_SOM_FB: C122.2 R133.1 R134.2 U24.2(FB)
V_SOM_L: C122.1 C135.2 C137.2 E8.2 E11.2 L11.2 Q7.1(S) Q7.2(S) Q7.3(S) R55.1 R133.2
V_SOM_LX: C119.2 L11.1 U24.6(SW)
V_SOM_PG: Q8.1(G) R131.2 U24.4(PGOOD)
V_SOM_PVCC: C124.1 U24.3(PVCC)
V_SOM_SS: C123.1 U24.14(SS)
VCOIN: BH1.2(PLUS) D11.ANODE
VDC_IN: C107.1 C108.1 C112.1 C113.1 C116.1 C117.1 C118.1 C131.1 C132.1 D7.CATHODE J3.1(CENTRAL) R131.1 R137.2 R154.1 U23.2(Vin) U24.7(VIN) U24.8(VIN) U25.2(Vin) ; also on sheet 1 2
VSB_1V5: C72.1 C80.1 C81.1 C82.1 C83.1 C84.1 C85.1 C86.1 P11.6(+1.5V_1) P11.28(+1.5V_2) P11.48(+1.5V_3) R81.2 R106.2 U12.7(Vout1) U12.8(Vout2)
VSB_1V5_EN: R104.2 R105.1 U12.4(EN)
VSB_1V8: C55.1 C62.2 C68.1 P8.11(DVDD1.8V/2.8V) R74.2 R76.2 R78.1 R79.2 R85.1 R90.2 R93.1 R97.2 U8.3(VCCA) U10.7(Vout1) U10.8(Vout2) ; also on sheet 9
VSB_1V8_PGOOD: R93.2 R99.2 U10.3(PGOOD)
VSB_2V8: C56.2 C57.1 C58.1 C70.1 P8.4(AVDD) P8.23(AF-VCC2.8V) R73.1 R82.1 R88.2 R101.1 R102.2 U11.7(Vout1) U11.8(Vout2)
VSB_2V8_EN: R99.1 R100.1 U11.4(EN)
VSB_2V8_PGOOD: R101.2 R104.1 U11.3(PGOOD)
VSOM_BP_EN#: E9.2 Q7.4(G) R55.2
VSOM_LED: DS2.ANODE R159.2

Not connected (* = marked no-connect by the designer): P8 7(NC)* 9(NC)* 17(NC)* 19(NC)* 21(NC)*; P10 4(RSVD4)* 8(RSVD8)*; P11 1(WAKE#)* 3(RSVD1)* 5(RSVD2)* 7(CLKREQ#)* 17(RSVD3)* 19(RSVD4)* 20(RSVD18)* 42(LED_WWAN#)* 43(RSVD8)* 44(LED_WLAN#)* 45(RSVD9)* 46(LED_WPAN#)* 47(RSVD10)* 49(RSVD11)* 51(RSVD12)*; P12 4(ID)*; P14 2* 4* 5* 6* 7*; P16 1* 6*; Q6 3(D2)* 4(S2)*; RN2 5(RD2)* 6(RC2)*; RN7 6(R5)* 9(R8)*; U9 2(FLG_A)* 3(FLG_B)* 4(EN_B)* 5(OUT_B)*; U12 3(PGOOD)*; U14 1(RI)* 10(NC)* 11(GPIO3)* 12(GPIO2)* 13(GPIO1)* 14(GPIO0)* 15(SUSPEND#)* 16(VPP)* 17(SUSPEND)* 18(CTS)* 19(RTS)* 22(DSR)* 23(DTR)* 24(DCD)*; U15 3(IO2)* 5(VBUS)*; U17 1(IO1)* 3(IO2)*; U18 2(R2IN)* 7(T2OUT)* 8(T3OUT)* 9(NC)* 11(T2IN)* 13(R5OUT)* 14(R4OUT)* 15(R3OUT)* 16(NC)* 17(R2OUT)* 19(R2OUTB)* 20(INVALID)* 25(NC)* 32(NC)*

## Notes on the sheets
sheet 10
- MIPI-CSI MODULE
  Based on SB-uCM design
- COMPATIBLE CAMERA MODULE: LI-OV5640-MIPI-AF
- Default I2C address (SCCB slave ID): 0x78
- DNP
- DNP
- DNP
- DNP
- DNP
- DNP
- DNP
- MCLK PROVISIONS
- DNP
- DNP
- up to 140mA
- DNP
- DNP
- DNP
- VSB_1V5, VSB_1V8 & VCC_2V8 CSI sources
- USB OTG
- >2.4
- Vout=Vfb*(1+Rt/Rb)=0.8*(1+13.3/10)=1.86V
- DNP
- DNP
- Vout=Vfb*(1+Rt/Rb)=0.8*(1+16.5/6.49)=2.8V
- mini PCIe & SIM
- Vout=Vfb*(1+Rt/Rb)=0.8*(1+9.1/10)=1.528V
- DNP
- DNP
- Validate if those resistors
  required after bring up
- Layout notes
  1: 100ohm differential impedance control for CSI, 85 for PCIe, 90 for USB.
  2: Match each differential signals pair ± 5 mils and 40 mils for usb
  3: Not more than two vias on each differential trace
  4: GND stitching VIA near every signal VIA
  5: The spacing between differential pair signal and other signals should at least three times the trace width.
sheet 11
- PRIMARY SERIAL
  DEBUG PORT
- FULL SIZE SD SLOT
  (BOOTABLE)
- DEBUG PORT
  (microUSB2.0 Type B)
  UART over USB
- 0R are kept as TP
  and for debug purposes
  Place on CS layer
- DNP
- O
- O
- Jumper removed: Automatic Mode
      Debug over USB when USB host
  provides VBUS
      Debug over RS-232 when USB VBUS not
  available
  Jumper assembled: Force RS232
- DNP
- DEBUG PORT
  (Compulab Proprietry)
  UART over RS-232
- TX
- RX
- D
- S
- G
- S
- D
- G
- RS485 - Half Duplex
- CARRIER BOARD EEPROM
- DNP
- 3.3V x 2mA = 6.6mW
- I2C slave address: 0x54..0x57
- REV 1.1 0 ohm res instead of REV 1.0's jumper for layout reasons
- Layout notes
  1: 120ohm differential impedance control for *485* signals.
  2: Match each differential signals pair ± 5 mils.
  3: Not more than two vias on each differential trace
  4: GND stitching VIA near every signal VIA
  5: The spacing between differential pair signal and other signals should at least three times the trace width.
sheet 12
- DC INPUT
- 5V0_PER
- RTC BATTERY
- 12V
- min 6.8uH
- Install by default
- H=4.2mm
- Vout=Vfb*(1+Rt/Rb)=
  0.92*(1+32.4/12.4)=3.32V@3A
- 12V domain
- up to 24V
- DNP
- V_SOM
- V_SOM DISCHARGE
- to 100 mill header
- 12V domain
- >1.6V
- Vout = 0.7x(1+Rup/Rdn)=0.7*(1+200/43.2)=3.94@9A
- Vin 4.5-18V
- Vgs up to 12V
- 10mA OD
- Current measure
- DNP
- 12V domain
- DNP
- 3V3_PER
- 3V3_AW
- STITCHING CAPACITORS
- H=4.2mm
- Vout=Vfb*(1+Rt/Rb)=
  0.92*(1+32.4/12.4)=3.32V@3A
- DNP
- DNP
- 12V domain
- DNP
- up to 24V
- DNP
- DNP
- 1206
